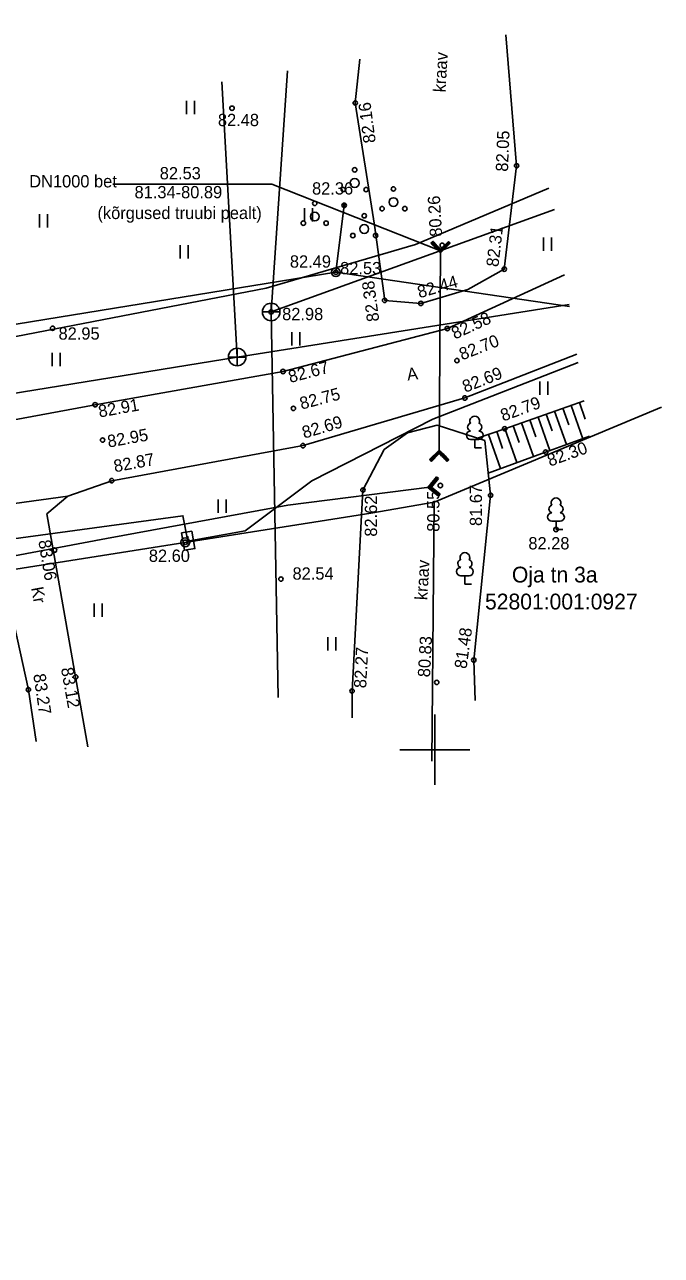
# Model space of a CAD drawing. Extents: x 648748 to 649126, y 6457789 to 6458252.
# Drawn here: x 649076.6 to 649112.9, y 6458121.2 to 6458191.3 of the extents above; entities that cross this region are included whole.
import ezdxf

# ---------------------------------------------------------------- set-up
doc = ezdxf.new("R2010")
doc.units = 0
for name, color, linetype in [('HALJASTUS', 7, 'Continuous'), ('KKAEV', 7, 'Continuous'), ('KORGUS-EH2000', 7, 'Continuous'), ('KTRASS', 7, 'Continuous'), ('MPOHULIIN', 7, 'Continuous'), ('PIIR', 7, 'Continuous'), ('POST', 7, 'Continuous'), ('PUU', 7, 'Continuous'), ('RELJEEF', 7, 'Continuous'), ('SIRAJATIS', 7, 'Continuous'), ('SITRASS', 7, 'Continuous'), ('SKTRASS', 7, 'Continuous'), ('TEE', 7, 'Continuous'), ('TRUUP', 7, 'Continuous'), ('VEEKOGU', 7, 'Continuous'), ('VORK', 7, 'Continuous')]:
    doc.layers.add(name, color=color, linetype=linetype)

msp = doc.modelspace()

# ---------------------------------------------------------------- linework, layer by layer
at = {"layer": 'HALJASTUS'}
for p, q in [((649085.853, 6458186.965), (649085.853, 6458186.204)), ((649086.308, 6458186.965), (649086.308, 6458186.204)), ((649077.475, 6458180.503), (649077.475, 6458179.742)), ((649077.93, 6458180.503), (649077.93, 6458179.742)), ((649092.579, 6458180.851), (649092.579, 6458180.09)), ((649093.034, 6458180.851), (649093.034, 6458180.09)), ((649106.2, 6458179.175), (649106.2, 6458178.414)), ((649106.655, 6458179.175), (649106.655, 6458178.414)), ((649085.484, 6458178.73), (649085.484, 6458177.969)), ((649085.939, 6458178.73), (649085.939, 6458177.969)), ((649091.853, 6458173.78), (649091.853, 6458173.019)), ((649092.308, 6458173.78), (649092.308, 6458173.019)), ((649078.186, 6458172.61), (649078.186, 6458171.849)), ((649078.641, 6458172.61), (649078.641, 6458171.849)), ((649105.998, 6458170.979), (649105.998, 6458170.218)), ((649106.453, 6458170.979), (649106.453, 6458170.218)), ((649087.652, 6458164.257), (649087.652, 6458163.496)), ((649088.107, 6458164.257), (649088.107, 6458163.496)), ((649080.592, 6458158.33), (649080.592, 6458157.569)), ((649081.047, 6458158.33), (649081.047, 6458157.569)), ((649093.907, 6458156.414), (649093.907, 6458155.653)), ((649094.362, 6458156.414), (649094.362, 6458155.653))]:
    msp.add_line(p, q, dxfattribs=at)
at = {"layer": 'KKAEV'}
for p, q in [((649090.171, 6458174.934), (649091.171, 6458174.934)), ((649090.671, 6458174.434), (649090.671, 6458175.434)), ((649088.736, 6458171.865), (649088.736, 6458172.865)), ((649088.236, 6458172.365), (649089.236, 6458172.365))]:
    msp.add_line(p, q, dxfattribs=at)
for centre in [(649090.671, 6458174.934), (649088.736, 6458172.365)]:
    msp.add_circle(centre, 0.5, dxfattribs=at)
at = {"layer": 'KORGUS-EH2000'}
for centre in [(649095.466, 6458186.841), (649088.44, 6458186.539), (649104.662, 6458183.264), (649094.836, 6458181.007), (649100.423, 6458178.727), (649094.361, 6458177.194), (649103.963, 6458177.37), (649097.144, 6458175.59), (649099.207, 6458175.421), (649090.671, 6458174.934), (649078.213, 6458174.002), (649100.717, 6458173.988), (649101.263, 6458172.162), (649091.348, 6458171.54), (649101.716, 6458170.032), (649080.638, 6458169.649), (649091.943, 6458169.438), (649103.985, 6458168.281), (649081.062, 6458167.634), (649092.488, 6458167.317), (649106.321, 6458166.952), (649081.585, 6458165.323), (649100.317, 6458165.048), (649095.902, 6458164.788), (649103.182, 6458164.491), (649106.911, 6458162.54), (649078.324, 6458161.366), (649085.777, 6458161.812), (649091.231, 6458159.718), (649102.224, 6458155.106), (649079.527, 6458154.141), (649100.11, 6458153.83), (649076.835, 6458153.415), (649095.284, 6458153.336)]:
    msp.add_circle(centre, 0.125, dxfattribs=at)
at = {"layer": 'KTRASS'}
for p, q in [((649091.595, 6458188.662), (649090.671, 6458174.934)), ((649087.868, 6458188.049), (649088.736, 6458172.365)), ((649090.671, 6458174.934), (649106.82, 6458180.774)), ((649088.736, 6458172.365), (649107.657, 6458175.367)), ((649090.671, 6458174.934), (649091.069, 6458152.975)), ((649088.736, 6458172.365), (649061.337, 6458167.918))]:
    msp.add_line(p, q, dxfattribs=at)
at = {"layer": 'MPOHULIIN'}
msp.add_lwpolyline([(648949.064, 6458178.85), (648980.689, 6458168.372), (648993.115, 6458162.488), (649016.276, 6458164.81), (649054.033, 6458170.656), (649094.361, 6458177.194), (649107.677, 6458175.236)], dxfattribs=at)
at = {"layer": 'PIIR'}
for p, q in [((649106.5, 6458181.99), (649098.91, 6458178.77)), ((649098.91, 6458178.77), (649090.38, 6458176.28)), ((649090.38, 6458176.28), (649067.87, 6458171.96)), ((649112.92, 6458169.505), (649099.97, 6458164.1)), ((649096.35, 6458163.48), (649099.97, 6458164.1)), ((649099.97, 6458164.1), (649099.83, 6458149.34)), ((649032.73, 6458153.43), (649096.35, 6458163.48))]:
    msp.add_line(p, q, dxfattribs=at)
at = {"layer": 'POST'}
msp.add_line((649094.836, 6458181.007), (649094.361, 6458177.194), dxfattribs=at)
for centre in [(649094.361, 6458177.194), (649085.777, 6458161.812)]:
    msp.add_circle(centre, 0.25, dxfattribs=at)
for start, end in [(0, 180), (180, 0)]:
    msp.add_arc((649094.836, 6458181.007), 0.0625, start, end, dxfattribs=at)
at = {"layer": 'PUU'}
for p, q in [((649102.519, 6458167.671), (649102.039, 6458167.671)), ((649102.279, 6458167.196), (649102.279, 6458167.671)), ((649102.659, 6458167.196), (649102.279, 6458167.196)), ((649107.151, 6458163.015), (649106.671, 6458163.015)), ((649106.911, 6458162.54), (649106.911, 6458163.015)), ((649107.291, 6458162.54), (649106.911, 6458162.54)), ((649101.956, 6458159.904), (649101.476, 6458159.904)), ((649101.716, 6458159.429), (649101.716, 6458159.904)), ((649102.096, 6458159.429), (649101.716, 6458159.429))]:
    msp.add_line(p, q, dxfattribs=at)
for centre, radius in [((649095.434, 6458182.278), 0.25), ((649095.434, 6458183.028), 0.125), ((649094.784, 6458181.903), 0.125), ((649096.084, 6458181.903), 0.125), ((649097.643, 6458181.941), 0.125), ((649093.156, 6458181.116), 0.125), ((649097.643, 6458181.191), 0.25), ((649093.156, 6458180.366), 0.25), ((649095.979, 6458180.41), 0.125), ((649096.993, 6458180.816), 0.125), ((649098.293, 6458180.816), 0.125), ((649092.506, 6458179.991), 0.125), ((649093.806, 6458179.991), 0.125), ((649095.979, 6458179.66), 0.25), ((649095.329, 6458179.285), 0.125), ((649096.629, 6458179.285), 0.125)]:
    msp.add_circle(centre, radius, dxfattribs=at)
for centre, radius, start, end in [((649102.108, 6458168.369), 0.233, 109.022, 253.142), ((649102.279, 6458168.716), 0.277, 332.58, 207.42), ((649102.449, 6458168.369), 0.233, 286.851, 70.986), ((649102.041, 6458167.909), 0.238, 90.002, 269.395), ((649102.516, 6458167.909), 0.238, 270.605, 89.998), ((649106.911, 6458164.06), 0.277, 332.58, 207.42), ((649106.741, 6458163.712), 0.233, 109.022, 253.142), ((649107.081, 6458163.712), 0.233, 286.851, 70.986), ((649106.673, 6458163.252), 0.238, 90.002, 269.395), ((649107.148, 6458163.252), 0.238, 270.605, 89.998), ((649101.546, 6458160.602), 0.233, 109.022, 253.142), ((649101.716, 6458160.949), 0.277, 332.58, 207.42), ((649101.886, 6458160.602), 0.233, 286.851, 70.986), ((649101.479, 6458160.142), 0.238, 90.002, 269.395), ((649101.954, 6458160.142), 0.238, 270.605, 89.998)]:
    msp.add_arc(centre, radius, start, end, dxfattribs=at)
at = {"layer": 'RELJEEF'}
for p, q in [((649107.501, 6458167.375), (649106.83, 6458169.281)), ((649107.637, 6458168.495), (649107.302, 6458169.447)), ((649108.442, 6458167.712), (649107.774, 6458169.613)), ((649108.579, 6458168.83), (649108.246, 6458169.778)), ((649105.62, 6458166.695), (649104.944, 6458168.618)), ((649105.752, 6458167.825), (649105.415, 6458168.784)), ((649106.559, 6458167.037), (649105.887, 6458168.949)), ((649106.694, 6458168.161), (649106.359, 6458169.115)), ((649103.741, 6458166.008), (649103.057, 6458167.954)), ((649103.87, 6458167.15), (649103.529, 6458168.12)), ((649104.68, 6458166.351), (649104, 6458168.286)), ((649104.811, 6458167.488), (649104.472, 6458168.452))]:
    msp.add_line(p, q, dxfattribs=at)
for points in [[(649108.508, 6458169.871), (649103.985, 6458168.281), (649102.443, 6458167.739)], [(649103.052, 6458165.756), (649106.321, 6458166.952), (649108.821, 6458167.849)]]:
    msp.add_lwpolyline(points, dxfattribs=at)
at = {"layer": 'SIRAJATIS'}
msp.add_lwpolyline([(649086.157, 6458162.443), (649086.322, 6458161.457), (649085.731, 6458161.358), (649085.566, 6458162.344)], close=True, dxfattribs=at)
for centre, radius in [((649085.911, 6458162.098), 0.0304), ((649085.911, 6458162.098), 0.029), ((649085.911, 6458162.098), 0.0277), ((649085.911, 6458162.098), 0.0263), ((649085.911, 6458162.098), 0.0249), ((649085.911, 6458162.098), 0.0236), ((649085.911, 6458162.098), 0.0222), ((649085.911, 6458162.098), 0.0209), ((649085.911, 6458162.098), 0.0195), ((649085.911, 6458162.098), 0.0181), ((649085.911, 6458162.098), 0.0168), ((649085.911, 6458162.098), 0.0154), ((649085.911, 6458162.098), 0.014), ((649085.911, 6458162.098), 0.0127), ((649085.911, 6458162.098), 0.0113), ((649085.911, 6458162.098), 0.00996), ((649085.911, 6458162.098), 0.0086), ((649085.911, 6458162.098), 0.00724), ((649085.911, 6458162.098), 0.00587), ((649085.911, 6458162.098), 0.00451), ((649085.911, 6458162.098), 0.00315), ((649085.911, 6458162.098), 0.00179), ((649085.911, 6458162.098), 0.000426), ((649085.977, 6458161.703), 0.0304), ((649085.977, 6458161.703), 0.029), ((649085.977, 6458161.703), 0.0277), ((649085.977, 6458161.703), 0.0263), ((649085.977, 6458161.703), 0.0249), ((649085.977, 6458161.703), 0.0236), ((649085.977, 6458161.703), 0.0222), ((649085.977, 6458161.703), 0.0209), ((649085.977, 6458161.703), 0.0195), ((649085.977, 6458161.703), 0.0181), ((649085.977, 6458161.703), 0.0168), ((649085.977, 6458161.703), 0.0154), ((649085.977, 6458161.703), 0.014), ((649085.977, 6458161.703), 0.0127), ((649085.977, 6458161.703), 0.0113), ((649085.977, 6458161.703), 0.00996), ((649085.977, 6458161.703), 0.0086), ((649085.977, 6458161.703), 0.00724), ((649085.977, 6458161.703), 0.00587), ((649085.977, 6458161.703), 0.00451), ((649085.977, 6458161.703), 0.00315), ((649085.977, 6458161.703), 0.00179), ((649085.977, 6458161.703), 0.000426)]:
    msp.add_circle(centre, radius, dxfattribs=at)
at = {"layer": 'SITRASS'}
for points in [[(649085.929, 6458161.874), (649089.19, 6458162.474), (649092.993, 6458165.317), (649099.885, 6458168.834), (649108.171, 6458172.046)], [(648995.643, 6458121.195), (648992.459, 6458125.184), (648989.418, 6458128.665), (648988.834, 6458130.069), (648992.568, 6458137.175), (649000.571, 6458151.371), (649010.371, 6458153.481), (649021.569, 6458155.012), (649033.911, 6458156.878), (649048.154, 6458158.873), (649059.027, 6458160.391), (649071.774, 6458161.431), (649085.639, 6458163.321), (649085.929, 6458161.874)]]:
    msp.add_lwpolyline(points, dxfattribs=at)
at = {"layer": 'SKTRASS'}
for p, q in [((649100.104, 6458165.54), (649099.608, 6458164.941)), ((649099.896, 6458165.066), (649099.609, 6458164.94)), ((649099.861, 6458165.023), (649099.63, 6458164.922)), ((649099.932, 6458165.109), (649099.642, 6458164.981)), ((649099.967, 6458165.151), (649099.677, 6458165.024)), ((649100.159, 6458165.495), (649099.708, 6458164.95)), ((649100.002, 6458165.194), (649099.713, 6458165.067)), ((649100.038, 6458165.237), (649099.748, 6458165.11)), ((649100.073, 6458165.28), (649099.783, 6458165.153)), ((649100.214, 6458165.449), (649099.808, 6458164.959)), ((649100.109, 6458165.322), (649099.819, 6458165.195)), ((649100.144, 6458165.365), (649099.854, 6458165.238)), ((649100.18, 6458165.408), (649099.89, 6458165.281)), ((649100.213, 6458165.45), (649099.926, 6458165.324)), ((649100.192, 6458165.467), (649099.961, 6458165.367)), ((649100.17, 6458165.485), (649099.996, 6458165.409)), ((649100.148, 6458165.504), (649100.032, 6458165.452)), ((649100.127, 6458165.521), (649100.067, 6458165.495)), ((649100.214, 6458165.449), (649100.104, 6458165.54)), ((649099.608, 6458164.941), (649100.207, 6458164.444)), ((649099.825, 6458164.98), (649099.652, 6458164.904)), ((649099.819, 6458164.95), (649099.673, 6458164.886)), ((649099.841, 6458164.932), (649099.695, 6458164.868)), ((649099.708, 6458164.95), (649100.253, 6458164.499)), ((649099.863, 6458164.914), (649099.716, 6458164.85)), ((649099.884, 6458164.897), (649099.738, 6458164.833)), ((649099.906, 6458164.879), (649099.759, 6458164.815)), ((649099.927, 6458164.861), (649099.781, 6458164.797)), ((649099.949, 6458164.843), (649099.803, 6458164.779)), ((649099.808, 6458164.959), (649100.298, 6458164.554)), ((649099.97, 6458164.825), (649099.824, 6458164.762)), ((649099.992, 6458164.807), (649099.846, 6458164.743)), ((649100.013, 6458164.789), (649099.867, 6458164.725)), ((649100.035, 6458164.772), (649099.889, 6458164.708)), ((649100.056, 6458164.754), (649099.911, 6458164.69)), ((649100.078, 6458164.736), (649099.932, 6458164.672)), ((649100.099, 6458164.718), (649099.954, 6458164.654)), ((649100.121, 6458164.7), (649099.975, 6458164.636)), ((649100.143, 6458164.682), (649099.997, 6458164.619)), ((649100.164, 6458164.664), (649100.018, 6458164.6)), ((649100.186, 6458164.646), (649100.04, 6458164.583)), ((649100.207, 6458164.629), (649100.062, 6458164.565)), ((649100.229, 6458164.611), (649100.083, 6458164.547)), ((649100.251, 6458164.593), (649100.105, 6458164.529)), ((649100.272, 6458164.575), (649100.126, 6458164.511)), ((649100.294, 6458164.557), (649100.148, 6458164.494)), ((649100.27, 6458164.52), (649100.169, 6458164.476)), ((649100.234, 6458164.477), (649100.191, 6458164.457)), ((649100.298, 6458164.554), (649100.207, 6458164.444))]:
    msp.add_line(p, q, dxfattribs=at)
msp.add_lwpolyline([(649003.97, 6458148.61), (649015.069, 6458149.564), (649019.431, 6458150.139), (649023.183, 6458151.111), (649025.815, 6458152.505), (649033.168, 6458154.063), (649043.179, 6458155.542), (649052.834, 6458156.983), (649065.23, 6458159.005), (649081.287, 6458162.038), (649091.624, 6458163.937), (649099.708, 6458164.95)], dxfattribs=at)
at = {"layer": 'TEE'}
for points in [[(649107.397, 6458177.046), (649100.717, 6458173.988), (649091.348, 6458171.54), (649080.638, 6458169.649), (649068.509, 6458167.394), (649058.16, 6458165.62), (649053.786, 6458164.971), (649038.247, 6458163.046), (649010.385, 6458159.395), (648991.816, 6458157.612), (648986.6, 6458158.516), (648983.403, 6458159.789), (648978.499, 6458164.674), (648956.171, 6458189.218), (648949.185, 6458196.386), (648941.448, 6458204.958), (648937.194, 6458209.825), (648934.521, 6458215.407), (648934.235, 6458222.731), (648937.629, 6458230.732), (648939.834, 6458235.213)], [(649002.881, 6458151.593), (649003.675, 6458152.941), (649070.906, 6458163.327), (649079.075, 6458164.441), (649081.585, 6458165.323), (649092.488, 6458167.317), (649101.716, 6458170.032), (649108.096, 6458172.531)], [(649079.075, 6458164.441), (649077.887, 6458163.427), (649079.527, 6458154.141), (649080.23, 6458150.161)], [(649077.28, 6458150.469), (649076.835, 6458153.415), (649075.548, 6458159.295), (649074.866, 6458160.615), (649073.445, 6458162.235), (649070.906, 6458163.327)]]:
    msp.add_lwpolyline(points, dxfattribs=at)
at = {"layer": 'TRUUP'}
for p, q in [((649099.881, 6458178.959), (649099.779, 6458178.859)), ((649099.779, 6458178.859), (649100.326, 6458178.306)), ((649099.8, 6458178.88), (649099.82, 6458178.818)), ((649099.82, 6458178.899), (649099.859, 6458178.778)), ((649099.83, 6458178.909), (649100.327, 6458178.406)), ((649099.84, 6458178.919), (649099.898, 6458178.739)), ((649099.86, 6458178.939), (649099.937, 6458178.699)), ((649099.88, 6458178.958), (649099.976, 6458178.66)), ((649099.881, 6458178.959), (649100.328, 6458178.507)), ((649099.918, 6458178.921), (649100.016, 6458178.62)), ((649099.957, 6458178.881), (649100.054, 6458178.58)), ((649099.997, 6458178.842), (649100.094, 6458178.541)), ((649100.035, 6458178.803), (649100.132, 6458178.501)), ((649100.075, 6458178.763), (649100.172, 6458178.462)), ((649100.113, 6458178.724), (649100.21, 6458178.422)), ((649100.153, 6458178.684), (649100.25, 6458178.383)), ((649100.191, 6458178.645), (649100.289, 6458178.343)), ((649100.231, 6458178.605), (649100.327, 6458178.306)), ((649100.327, 6458178.406), (649100.256, 6458166.966)), ((649100.27, 6458178.566), (649100.347, 6458178.326)), ((649100.309, 6458178.526), (649100.367, 6458178.345)), ((649100.326, 6458178.306), (649100.88, 6458178.852)), ((649100.327, 6458178.406), (649100.83, 6458178.903)), ((649100.328, 6458178.507), (649100.78, 6458178.954)), ((649100.338, 6458178.517), (649100.387, 6458178.365)), ((649100.358, 6458178.537), (649100.407, 6458178.385)), ((649100.378, 6458178.556), (649100.427, 6458178.405)), ((649100.397, 6458178.576), (649100.447, 6458178.424)), ((649100.418, 6458178.596), (649100.467, 6458178.444)), ((649100.437, 6458178.616), (649100.486, 6458178.464)), ((649100.457, 6458178.635), (649100.506, 6458178.484)), ((649100.477, 6458178.655), (649100.526, 6458178.503)), ((649100.497, 6458178.675), (649100.546, 6458178.523)), ((649100.517, 6458178.694), (649100.566, 6458178.542)), ((649100.537, 6458178.714), (649100.586, 6458178.562)), ((649100.557, 6458178.733), (649100.606, 6458178.582)), ((649100.577, 6458178.753), (649100.626, 6458178.601)), ((649100.597, 6458178.773), (649100.646, 6458178.621)), ((649100.617, 6458178.792), (649100.666, 6458178.641)), ((649100.636, 6458178.812), (649100.685, 6458178.66)), ((649100.657, 6458178.832), (649100.706, 6458178.68)), ((649100.677, 6458178.852), (649100.725, 6458178.7)), ((649100.696, 6458178.871), (649100.745, 6458178.72)), ((649100.716, 6458178.891), (649100.765, 6458178.739)), ((649100.736, 6458178.911), (649100.785, 6458178.759)), ((649100.756, 6458178.93), (649100.805, 6458178.778)), ((649100.776, 6458178.95), (649100.825, 6458178.798)), ((649100.78, 6458178.954), (649100.88, 6458178.852)), ((649100.811, 6458178.922), (649100.845, 6458178.818)), ((649100.85, 6458178.882), (649100.865, 6458178.837)), ((649100.257, 6458167.066), (649099.703, 6458166.52)), ((649099.804, 6458166.418), (649099.703, 6458166.52)), ((649099.733, 6458166.49), (649099.718, 6458166.535)), ((649099.772, 6458166.45), (649099.738, 6458166.554)), ((649100.256, 6458166.966), (649099.753, 6458166.469)), ((649099.808, 6458166.422), (649099.758, 6458166.574)), ((649099.827, 6458166.442), (649099.778, 6458166.594)), ((649099.847, 6458166.462), (649099.798, 6458166.613)), ((649100.256, 6458166.866), (649099.804, 6458166.418)), ((649099.867, 6458166.481), (649099.818, 6458166.633)), ((649099.887, 6458166.501), (649099.838, 6458166.653)), ((649099.907, 6458166.521), (649099.858, 6458166.672)), ((649099.927, 6458166.541), (649099.878, 6458166.692)), ((649099.947, 6458166.56), (649099.898, 6458166.712)), ((649099.967, 6458166.58), (649099.917, 6458166.732)), ((649099.987, 6458166.6), (649099.938, 6458166.751)), ((649100.006, 6458166.619), (649099.958, 6458166.771)), ((649100.026, 6458166.639), (649099.977, 6458166.79)), ((649100.046, 6458166.658), (649099.997, 6458166.81)), ((649100.066, 6458166.678), (649100.017, 6458166.83)), ((649100.086, 6458166.698), (649100.037, 6458166.849)), ((649100.106, 6458166.717), (649100.057, 6458166.869)), ((649100.126, 6458166.737), (649100.077, 6458166.889)), ((649100.146, 6458166.757), (649100.097, 6458166.908)), ((649100.166, 6458166.777), (649100.117, 6458166.928)), ((649100.186, 6458166.796), (649100.137, 6458166.948)), ((649100.205, 6458166.816), (649100.156, 6458166.968)), ((649100.226, 6458166.836), (649100.177, 6458166.987)), ((649100.246, 6458166.855), (649100.197, 6458167.007)), ((649100.275, 6458166.846), (649100.216, 6458167.027)), ((649100.313, 6458166.807), (649100.236, 6458167.046)), ((649100.353, 6458166.767), (649100.256, 6458167.066)), ((649100.753, 6458166.463), (649100.256, 6458166.966)), ((649100.702, 6458166.413), (649100.256, 6458166.866)), ((649100.804, 6458166.513), (649100.257, 6458167.066)), ((649100.392, 6458166.728), (649100.294, 6458167.029)), ((649100.431, 6458166.688), (649100.334, 6458166.989)), ((649100.47, 6458166.649), (649100.373, 6458166.95)), ((649100.509, 6458166.609), (649100.412, 6458166.91)), ((649100.548, 6458166.57), (649100.451, 6458166.871)), ((649100.587, 6458166.53), (649100.49, 6458166.831)), ((649100.626, 6458166.491), (649100.529, 6458166.792)), ((649100.665, 6458166.451), (649100.568, 6458166.752)), ((649100.704, 6458166.414), (649100.607, 6458166.712)), ((649100.723, 6458166.433), (649100.646, 6458166.673)), ((649100.743, 6458166.453), (649100.685, 6458166.633)), ((649100.702, 6458166.413), (649100.804, 6458166.513)), ((649100.763, 6458166.473), (649100.724, 6458166.594)), ((649100.783, 6458166.492), (649100.763, 6458166.554))]:
    msp.add_line(p, q, dxfattribs=at)
msp.add_lwpolyline([(649081.644, 6458182.206), (649090.713, 6458182.206), (649100.327, 6458178.406)], dxfattribs=at)
at = {"layer": 'VEEKOGU'}
for points in [[(649104.055, 6458190.709), (649104.662, 6458183.264), (649103.963, 6458177.37), (649101.882, 6458176.205), (649099.207, 6458175.421), (649097.144, 6458175.59), (649096.571, 6458179.87), (649095.466, 6458186.841), (649095.719, 6458189.339)], [(649095.288, 6458151.808), (649095.284, 6458153.336), (649095.902, 6458164.788), (649097.111, 6458167.098), (649098.437, 6458168.047), (649100.138, 6458168.476), (649102.846, 6458167.61), (649103.182, 6458164.491), (649102.224, 6458155.106), (649102.303, 6458152.793)]]:
    msp.add_lwpolyline(points, dxfattribs=at)
at = {"layer": 'VORK'}
for p, q in [((649100, 6458152), (649100, 6458148)), ((649098, 6458150), (649102, 6458150))]:
    msp.add_line(p, q, dxfattribs=at)

# ---------------------------------------------------------------- texts
at = {"layer": 'KORGUS-EH2000'}
for s, rotation, p in [('82.16', 97.6201, (649096.641, 6458184.595)), ('82.05', 87.73659, (649104.171, 6458182.913)), ('80.26', 93.36646, (649100.425, 6458179.238)), ('82.31', 83.2398, (649103.623, 6458177.472)), ('82.44', 16.34012, (649099.126, 6458175.707)), ('82.38', 97.62743, (649096.841, 6458174.422)), ('82.58', 24.5976, (649101.147, 6458173.357)), ('82.70', 21.39171, (649101.556, 6458172.169)), ('82.67', 14.64079, (649091.755, 6458170.885)), ('82.69', 21.39171, (649101.739, 6458170.325)), ('82.75', 14.64079, (649092.403, 6458169.368)), ('82.91', 10.01213, (649080.884, 6458168.917)), ('82.79', 19.98311, (649103.898, 6458168.688)), ('82.69', 16.39579, (649092.553, 6458167.714)), ('82.95', 10.01213, (649081.399, 6458167.206)), ('82.30', 19.81148, (649106.564, 6458166.119)), ('82.87', 10.36135, (649081.76, 6458165.798)), ('81.67', 90, (649102.692, 6458162.739)), ('82.62', 90, (649096.708, 6458162.133)), ('80.55', 90, (649100.266, 6458162.41)), ('83.06', 279.44483, (649077.397, 6458161.898)), ('81.48', 81.96429, (649101.807, 6458154.581)), ('80.83', 86.91212, (649099.726, 6458154.112)), ('82.27', 86.91212, (649096.086, 6458153.489)), ('83.12', 280.02278, (649078.688, 6458154.628)), ('83.27', 278.58873, (649077.108, 6458154.28))]:
    msp.add_text(s, height=0.7, rotation=rotation, dxfattribs=at).set_placement(p)
for s, p in [('82.48', (649087.637, 6458185.518)), ('82.36', (649093.004, 6458181.62)), ('82.49', (649091.74, 6458177.458)), ('82.53', (649094.605, 6458177.079)), ('82.98', (649091.299, 6458174.464)), ('82.95', (649078.551, 6458173.356)), ('82.28', (649105.336, 6458161.409)), ('82.60', (649083.699, 6458160.698)), ('82.54', (649091.89, 6458159.685))]:
    msp.add_text(s, height=0.7, dxfattribs=at).set_placement(p)
at = {"layer": 'PIIR'}
for s, p in [('Oja tn 3a', (649104.397, 6458159.523)), ('52801:001:0927', (649102.864, 6458157.987))]:
    msp.add_text(s, height=0.9, rotation=360, dxfattribs=at).set_placement(p)
at = {"layer": 'TEE'}
for s, rotation, p in [('A', 7.04935, (649098.454, 6458171.024)), ('Kr', 280.34951, (649076.984, 6458159.216))]:
    msp.add_text(s, height=0.7, rotation=rotation, dxfattribs=at).set_placement(p)
at = {"layer": 'TRUUP'}
for s, p in [('DN1000 bet', (649076.88, 6458182.028)), ('82.53', (649084.321, 6458182.487)), ('81.34-80.89', (649082.884, 6458181.408)), ('(kõrgused truubi pealt)', (649080.771, 6458180.225))]:
    msp.add_text(s, height=0.7, dxfattribs=at).set_placement(p)
at = {"layer": 'VEEKOGU'}
for p in [(649100.608, 6458187.427), (649099.567, 6458158.504)]:
    msp.add_text('kraav', height=0.7, rotation=86.59347, dxfattribs=at).set_placement(p)

doc.saveas('drawing.dxf')
